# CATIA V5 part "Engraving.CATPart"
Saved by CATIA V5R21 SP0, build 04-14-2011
Part number: LCD
Bounding box of the stored display mesh (mm): x -92.6 to 92.6, y -50 to 50, z 0 to 2.8
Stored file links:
  C:\Users\Pouria\Desktop\Engraving.CATPart
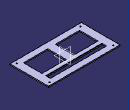
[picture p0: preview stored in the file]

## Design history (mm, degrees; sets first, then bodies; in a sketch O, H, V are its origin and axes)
Body1 (main body)
  Sketch1 on xy-plane, origin (0, 0, 0), H (1, 0, 0), V (0, 1, 0)
    line L1 (92.8, 50) -> (92.8, 20)
    line L2 (92.8, -50) -> (-92.8, -50)
    line L3 (-92.8, -50) -> (-92.8, -20)
    line L4 (-92.8, 50) -> (92.8, 50)
    point P1 (92.8, 50)
    point P2 (92.8, -50)
    line L5 (9.8, 13) -> (72.8, 13)
    line L6 (72.8, 13) -> (72.8, -35)
    line L7 (72.8, -35) -> (9.8, -35)
    line L8 (9.8, -35) -> (9.8, 13)
    line L9 (92.8, 20) -> (90, 20)
    line L10 (90, 20) -> (90, -20)
    line L11 (90, -20) -> (92.8, -20)
    point P12 (92.8, -20)
    point P13 (-92.8, 20)
    line L12 (-92.8, 20) -> (-90, 20)
    line L13 (-90, 20) -> (-90, -20)
    line L14 (-90, -20) -> (-92.8, -20)
    line L15 (92.8, -20) -> (92.8, -50)
    line L16 (-92.8, 20) -> (-92.8, 50)
    circle A1 centre (82.5, -42.5) radius 1.5
    point P17 (82.5, -42.5)
    circle A2 centre (82.5, 42.5) radius 1.5
    point P18 (82.5, 42.5)
    circle A3 centre (-82.5, 42.5) radius 1.5
    point P19 (-82.5, 42.5)
    circle A4 centre (-82.5, -42.5) radius 1.5
    point P20 (-82.5, -42.5)
    length L4 = 185.6
    length L5 = 63
    length L6 = 48
    distance L2 L7 = 15
    length L9 = 2.8
    length L13 = 40
    distance P1 P2 = 100
    distance L1 L6 = 20
    distance P17 L2 = 7.5
    distance P17 L10 = 7.5
    distance P20 L13 = 7.5
    distance P20 L2 = 7.5
    distance P19 L4 = 7.5
    distance P19 L13 = 7.5
    distance P18 L4 = 7.5
    distance P18 L10 = 7.5
    radius A2 = 1.5
    radius A3 = 1.5
    radius A4 = 1.5
    radius A1 = 1.5
    vertical: L1 V, L3 V, L6 V, L8 V, L10 V, L13 V, L15 V, L16 V
    horizontal: L2 H, L4 H, L5 H, L7 H, L9 H, L11 H, L12 H, L14 H
    equidistance: L1 L3 O, L2 L4 O
    coincidence: P12 L1, P13 L3, L9 L12, L11 L14, L1 L15, L3 L16
    symmetry: L12 L14 H, L11 L9 H, L10 L13 V
  Pad1: profile Sketch1, direction (0, 0, 1), length 2.8
  Sketch2 on end face of Pad1, origin (0, 0, 2.8), H (1, 0, 0), V (0, 1, 0)
    circle A1 centre (76.55, -33.1) radius 1.6
    point P1 (76.55, -33.1)
    circle A2 centre (0.65, -33.1) radius 1.6
    point P2 (0.65, -33.1)
    circle A3 centre (0.65, 11.1) radius 1.6
    point P3 (0.65, 11.1)
    circle A4 centre (76.55, 11.1) radius 1.6
    point P4 (76.55, 11.1)
    radius A4 = 1.6
    radius A1 = 1.6
    radius A3 = 1.6
    radius A2 = 1.6
    distance P3 V = 0.65
    distance P3 H = 11.1
    distance P2 V = 0.65
    distance P2 H = 33.1
    distance P1 V = 76.55
    distance P1 H = 33.1
    distance P4 V = 76.55
    distance P4 H = 11.1
  Pocket1: profile Sketch2, direction (0, 0, -1), through (limit type 6)
  Sketch3 on end face of Pad1, origin (0, 0, 2.8), H (1, 0, 0), V (0, 1, 0)
    line L1 (72.8, 25.4528) -> (92.8, 25.4528)
    line L2 (92.8, 25.4528) -> (92.8, -36.367)
    line L3 (92.8, -36.367) -> (72.8, -36.367)
    line L4 (72.8, -36.367) -> (72.8, 25.4528)
    line L5 (9.8, -37.5525) -> (-92.8, -37.5525)
    line L6 (-92.8, -37.5525) -> (-92.8, 31.2114)
    line L7 (-92.8, 31.2114) -> (9.8, 31.2114)
    line L8 (9.8, 31.2114) -> (9.8, -37.5525)
    reference projected line E1 (92.8, 20) -> (92.8, 50) from edge [face of Pad1 from Sketch1.L1 | end face of Pad1]
    reference projected line E2 (72.8, -35) -> (72.8, 13) from edge [end face of Pad1 | face of Pad1 from Sketch1.L6]
    reference projected line E3 (9.8, 13) -> (9.8, -35) from edge [end face of Pad1 | face of Pad1 from Sketch1.L8]
    reference projected line E4 (-92.8, -20) -> (-92.8, -50) from edge [face of Pad1 from Sketch1.L3 | end face of Pad1]
    horizontal: L1 H, L3 H, L5 H, L7 H
    vertical: L2 V, L4 V, L6 V, L8 V
    coincidence: L2 E1, L4 E2, L8 E3, L6 E4
  Pad2: profile Sketch3, direction (0, 0, 1), up to start face of Pad1
  Sketch4 on face of Pad1, origin (0, 0, 2.8), H (1, 0, 0), V (0, 1, 0)
    line L1 (110.9869, 58.4596) -> (92.6, 58.4596)
    line L2 (92.6, 58.4596) -> (92.6, -63.793)
    line L3 (92.6, -63.793) -> (110.9869, -63.793)
    line L4 (110.9869, -63.793) -> (110.9869, 58.4596)
    line L5 (-110.9869, 61.7426) -> (-92.6, 61.7426)
    line L6 (-92.6, 61.7426) -> (-92.6, -53.006)
    line L7 (-92.6, -53.006) -> (-110.9869, -53.006)
    line L8 (-110.9869, -53.006) -> (-110.9869, 61.7426)
    reference projected line E1 (-92.8, -50) -> (-92.8, -20) from edge [face of Pad1 | face of Pad1]
    reference projected line E3 (92.8, -20) -> (92.8, -50) from edge [face of Pad1 | face of Pad1]
    distance L6 E1 = 0.2
    distance L2 E3 = 0.2
    horizontal: L1 H, L3 H, L5 H, L7 H
    vertical: L2 V, L4 V, L6 V, L8 V
  Pocket2: profile Sketch4, direction (0, 0, -1), through (limit type 3)
  Sketch5 on face of Pad1, origin (0, 0, 2.8), H (1, 0, 0), V (0, 1, 0)
    line L1 (-72.8, 35) -> (72.8, 35)
    line L2 (72.8, 35) -> (72.8, 23)
    line L3 (72.8, 23) -> (-72.8, 23)
    line L4 (-72.8, 23) -> (-72.8, 35)
    line L5 (-72.8, 13) -> (-9.8, 13)
    line L6 (-9.8, 13) -> (-9.8, -35)
    line L7 (-9.8, -35) -> (-72.8, -35)
    line L8 (-72.8, -35) -> (-72.8, 13)
    reference projected line E1 (9.8, -35) -> (72.8, -35) from edge [face of Pad1 | face of Pad1 from Sketch1.L7]
    reference projected line E2 (-92.8, -50) -> (92.8, -50) from edge [face of Pad1 from Sketch1.L2 | face of Pad1]
    reference projected line E3 (92.8, 50) -> (-92.8, 50) from edge [face of Pad1 from Sketch1.L4 | face of Pad1]
    reference projected line E4 (-92.8, -50) -> (92.8, -50) from edge [face of Pad1 from Sketch1.L2 | face of Pad1]
    reference projected line E5 (72.8, 13) -> (72.8, -35) from edge [face of Pad2 | face of Pad1]
    reference projected line E6 (92.6, 50) -> (92.6, -50) from edge [face of Pad1 | face of Pocket2 from Sketch4.L2]
    reference projected line E7 (-92.6, -50) -> (-92.6, 50) from edge [face of Pad1 | face of Pocket2 from Sketch4.L6]
    reference projected line E8 (72.8, 13) -> (9.8, 13) from edge [face of Pad1 | face of Pad1 from Sketch1.L5]
    reference projected line E9 (9.8, -35) -> (72.8, -35) from edge [face of Pad1 | face of Pad1 from Sketch1.L7]
    reference projected line E10 (72.8, 13) -> (72.8, -35) from edge [face of Pad2 | face of Pad1]
    reference projected line E11 (9.8, -35) -> (9.8, 13) from edge [face of Pad2 | face of Pad1]
    reference projected line E12 (72.8, 13) -> (72.8, -35) from edge [face of Pad2 | face of Pad1]
    distance E1 E2 = 15 (reference)
    distance L1 E3 = 15
    distance L7 E4 = 15
    distance E5 E6 = 19.8 (reference)
    distance L8 E7 = 19.8
    distance E8 E9 = 48 (reference)
    distance E10 E11 = 63 (reference)
    distance L6 L8 = 63
    distance L7 L5 = 48
    length L2 = 12
    horizontal: L1 H, L3 H, L5 H, L7 H
    vertical: L2 V, L4 V, L6 V, L8 V
    coincidence: L2 E12, L4 L8
  Pocket3: profile Sketch5, direction (0, 0, -1), through (limit type 3)
  Sketch6 on face of Pad1, origin (0, 0, 2.8), H (1, 0, 0), V (0, 1, 0)
    line L1 (-72.7, 24.6) -> (72.7, 24.6)
    line L2 (72.7, 24.6) -> (72.7, 23.1)
    line L3 (72.7, 23.1) -> (-72.7, 23.1)
    line L4 (-72.7, 23.1) -> (-72.7, 24.6)
    reference projected line E1 (72.8, 23) -> (72.8, 35) from edge [face of Pad1 | face of Pocket3 from Sketch5.L2]
    reference projected line E2 (-72.8, 35) -> (-72.8, 23) from edge [face of Pad1 | face of Pocket3 from Sketch5.L4]
    reference projected line E3 (-72.8, 23) -> (72.8, 23) from edge [face of Pad1 | face of Pocket3 from Sketch5.L3]
    distance L2 E1 = 0.1
    distance L4 E2 = 0.1
    distance L3 E3 = 0.1
    distance L1 L3 = 1.5
    horizontal: L1 H, L3 H
    vertical: L2 V, L4 V
  Pad3: profile Sketch6, direction (0, 0, 1), up to face of Pad1
  Fillet1: radius 0.5, on edge [face of Pad3 from Sketch6.L2 | face of Pad3 from Sketch6.L1]; edge [face of Pad3 from Sketch6.L3 | face of Pad3 from Sketch6.L2]; edge [face of Pad3 from Sketch6.L1 | face of Pad3 from Sketch6.L4]; edge [face of Pad3 from Sketch6.L4 | face of Pad3 from Sketch6.L3]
